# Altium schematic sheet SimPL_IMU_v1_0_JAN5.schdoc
size 302 x 236 mm
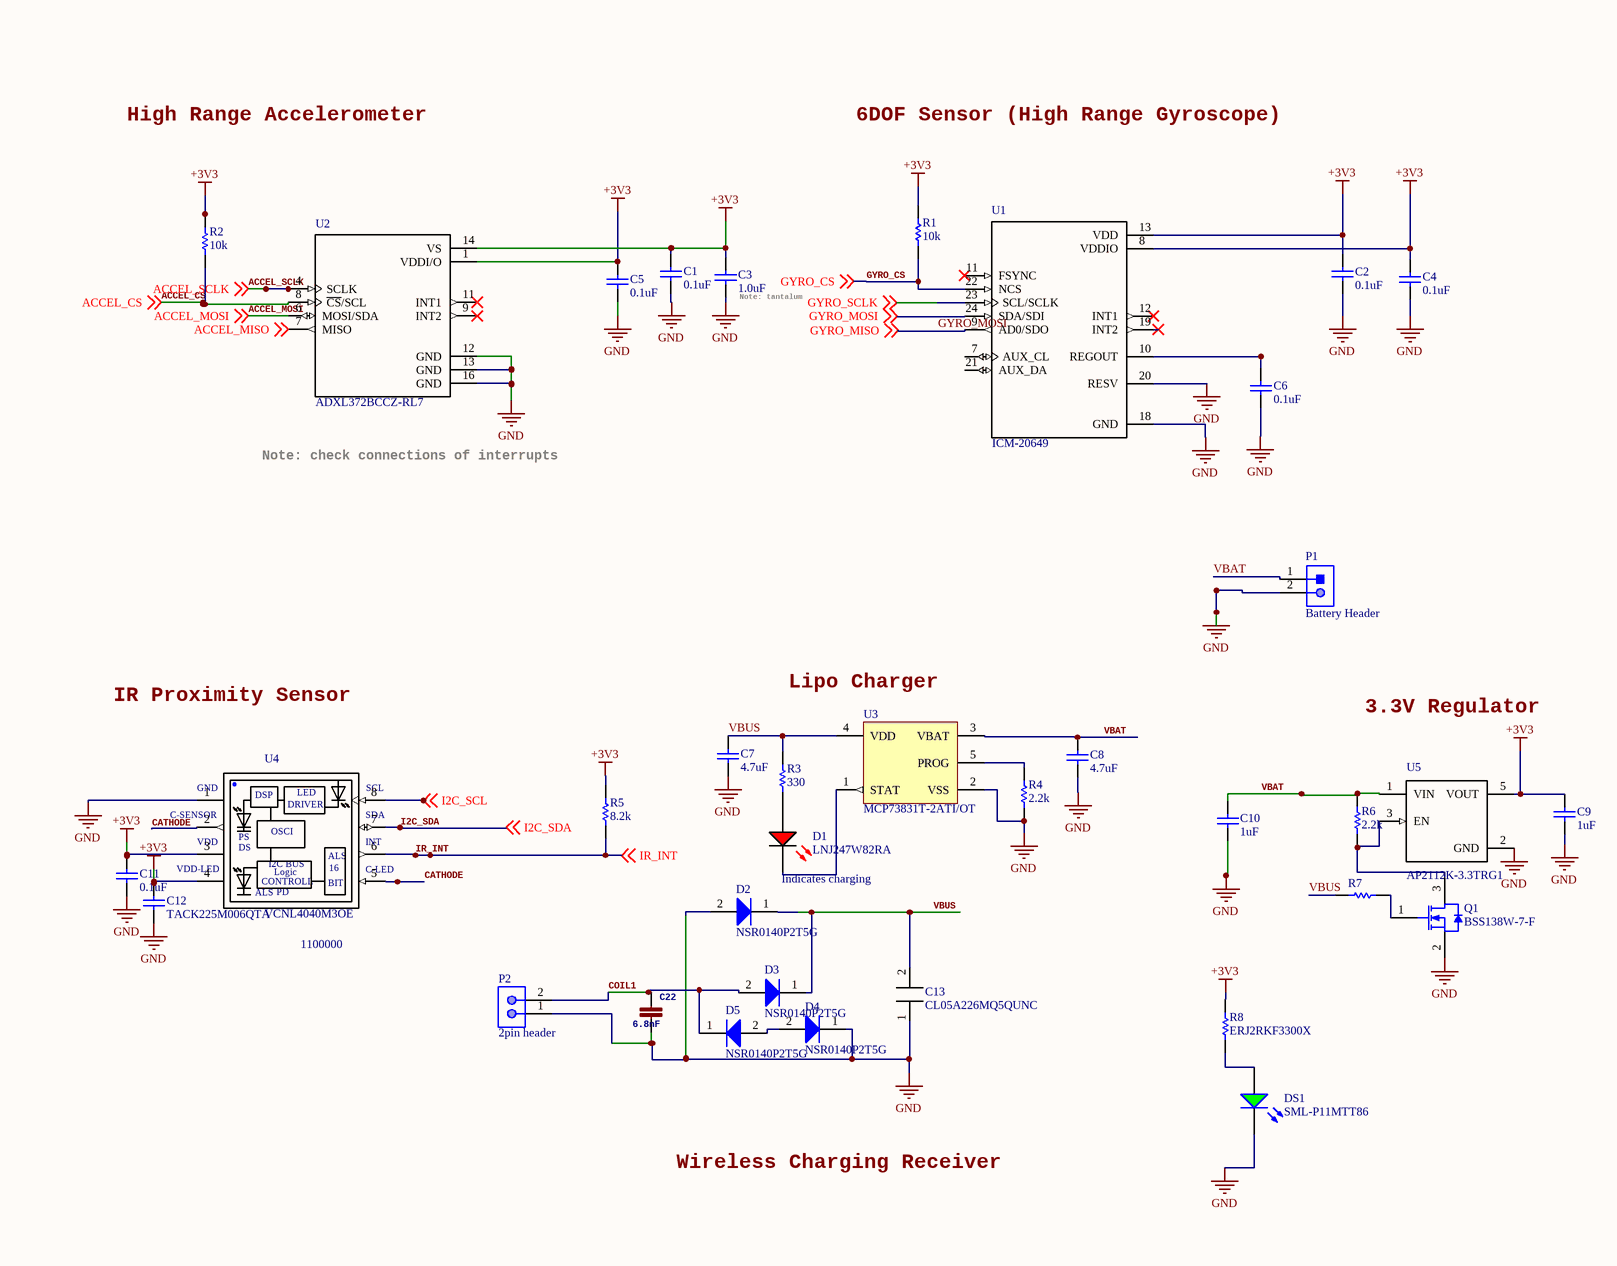
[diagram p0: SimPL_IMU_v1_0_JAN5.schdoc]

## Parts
C1  0.1uF  [CAPC0603X33X15LL03T05]
C2  0.1uF  [CAPC0603X33X15LL03T05]
C3  1.0uF  [CAPC1005X70X10LL20T00]
C4  0.1uF  [CAPC0603X33X15LL03T05]
C5  0.1uF  [CAPC0603X33X15LL03T05]
C6  0.1uF  [CAPC0603X33X15LL03T05]
C7  4.7uF  [CAPC1005X55X25NL05T10]
C8  4.7uF  [CAPC1005X55X25NL05T10]
C9  1uF  [CAPC1005X55X25NL05T10]
C10  1uF  [CAPC1005X55X25NL05T10]
C11  0.1uF  [CAPC0603X33X15LL03T05]
C12  TACK225M006QTA  [CAPC1005X70X10NL20T00]
C13  CL05A226MQ5QUNC  [*CAPC1005X55N]
C22  6.8nF  [0402]
D1  LNJ247W82RA  [PNSC-CHIP-2_V]
D2  NSR0140P2T5G  [ONSC-SOD-923-2-514AA-01_D_V]
D3  NSR0140P2T5G  [ONSC-SOD-923-2-514AA-01_D_V]
D4  NSR0140P2T5G  [ONSC-SOD-923-2-514AA-01_D_V]
D5  NSR0140P2T5G  [ONSC-SOD-923-2-514AA-01_D_V]
DS1  SML-P11MTT86  [ROHM-SML-P11MT_V]
P1  Battery Header  [JST-S2B-PH-K-S_V]
P2  2pin header  [AMPH-68000-102HLF_V]
Q1  BSS138W-7-F  [DIOD-SOT323-3_V]
R1  10k  [RESC0603X26X15NL03T05]
R2  10k  [RESC0603X26X15NL03T05]
R3  330  [RESC1005X40X25NL05T05]
R4  2.2k  [RESC1005X40X25NL10T10]
R5  8.2k  [RESC0201(0603)_L]
R6  2.2k  [RESC1005X40X25NL10T10]
R7  CRCW04022K20FKED  [RESC1005X40X25NL05T05]  (value not drawn)
R8  ERJ2RKF3300X  [RESC1005X40X25ML05T05]
U1  ICM-20649  [*QFN40P300X300X95-24N]
U2  ADXL372BCCZ-RL7  [*PQFN50P322X300X114-16N]
U3  MCP73831T-2ATI/OT  [SOT-23-OT5_M]
U4  VCNL4040M3OE  [*VISHAY_VCNL4040_4X2X1.1]
U5  AP2112K-3.3TRG1  [*SOT95P285X140-5N]

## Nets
+3V3: C1.2 C2.2 C3.2 C4.2 C5.2 C9.2 C11.2 C12.2 R1.2 R2.2 R5.2 R8.2 U1.8(VDDIO) U1.13(VDD) U2.1(VDDI/O) U2.14(VS) U4.3(VDD) U4.4(VDD-LED) U5.5(VOUT)
GND: C1.1 C2.1 C3.1 C4.1 C5.1 C6.1 C7.1 C8.1 C9.1 C10.1 C11.1 C12.1 C13.1 C22.2 D2.2(A) D4.1(K) DS1.2(K) P1.2 P2.1 Q1.2(S) R4.1 U1.18(GND) U1.20(RESV) U2.12(GND) U2.13(GND) U2.16(GND) U3.2(VSS) U4.1(GND) U5.2(GND)
ACCEL_CS: R2.1 U2.8(~{CS}/SCL) ; off-sheet ACCEL_CS
ACCEL_MISO: U2.7(MISO) ; off-sheet ACCEL_MISO
ACCEL_MOSI: U2.6(MOSI/SDA) ; off-sheet ACCEL_MOSI
ACCEL_SCLK: U2.4(SCLK) ; off-sheet ACCEL_SCLK
CATHODE: U4.2(C-SENSOR) U4.5(C-LED)
COIL1: C22.1 D3.2(A) D5.1(K) P2.2
GYRO_CS: R1.1 U1.22(NCS) ; off-sheet GYRO_CS
GYRO_MOSI: U1.9(AD0/SDO) U1.24(SDA/SDI) ; off-sheet GYRO_MISO, off-sheet GYRO_MOSI  [also labelled GYRO_MISO]
GYRO_SCLK: U1.23(SCL/SCLK) ; off-sheet GYRO_SCLK
I2C_SCL: U4.8(SCL) ; off-sheet I2C_SCL
I2C_SDA: U4.7(SDA) ; off-sheet I2C_SDA
IR_INT: R5.1 U4.6(INT) ; off-sheet IR_INT
VBAT: C8.2 C10.2 P1.1 R6.2 U3.3(VBAT) U5.1(VIN)
VBUS: C7.2 C13.2 D2.1(K) D3.1(K) R3.2 R7.1 U3.4(VDD)
NetC6_2: C6.2 U1.10(REGOUT)
NetD1_1: D1.1(ANODE) R3.1
NetD1_2: D1.2(CATHODE) U3.1(STAT)
NetD4_2: D4.2(A) D5.2(A)
NetDS1_1: DS1.1(A) R8.1
NetQ1_1: Q1.1(G) R7.2
NetQ1_3: Q1.3(D) R6.1 U5.3(EN)
NetR4_2: R4.2 U3.5(PROG)

Not connected (* = marked no-connect by the designer): U1 7(AUX_CL) 11(FSYNC)* 12(INT1)* 19(INT2)* 21(AUX_DA); U2 9(INT2)* 11(INT1)*

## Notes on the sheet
- High Range Accelerometer
- 6DOF Sensor (High Range Gyroscope)
- (near C3) Note: tantalum
- Note: check connections of interrupts
- IR Proximity Sensor
- (near U3) Lipo Charger
- 3.3V Regulator
- Indicates charging
- 1100000
- Wireless Charging Receiver
- Labels drawn without touching a wire or pin: I2C_SDA

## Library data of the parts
C1 C2 C4-C6 C11 = CMP-2010-01264-1: Part Number: GRM033R61A104KE15D; Manufacturer: Murata
C3 = CMP-2008-00066-1: Part Number: TACK105M010QTA; Manufacturer: AVX Interconnect / Elco
C7 C8 = CMP-2008-04549-1: Part Number: GRM155R60J475ME47D; Manufacturer: Murata
C9 C10 = CMP-2008-04556-1: Part Number: GRM155R61A105KE15D; Manufacturer: Murata
C12 = CMP-2008-00070-1: Manufacturer: AVX Interconnect / Elco
C13 = CL05A226MQ5QUNC: Capacitance: 22uF
C22 = 0.1UF-0402-16V-10%: 0.1ÂµF ceramic capacitors    A capacitor is a passive two-terminal electrical component used to store electrical energy temporarily in an electric field.; Part Number: CC0402KRX7R9BB682; GateName_1: G$1; SymbolName_1: CAP; DeviceSetName: 0.1UF; PROD_ID: CAP-12416
D1 = CMP-0456-00001-2: Hight Bright Surface Mounting Chip LED (Red), 55 mW, -30 to 85 degC, 1.0 x 0.5 x 0.2 mm  SMD; Manufacturer: Panasonic; Forward Voltage: 1.95 V; Reverse Current: 100 uA; Spectral half band width: 20 nm; Dominant Emission Wavelength: 630 nm; Luminous Intensity: 16 mcd; Peak Emission Wavelength: 645 nm
D2-D5 = CMP-1055-00493-1: Schottky Barrier Diode, 2-Pin SOD-923, Pb-Free, Tape and Reel; Manufacturer: On Semiconductor; IFSM Max (A): 0.5; Configuration: Single
DS1 = CMP-2000-07126-1: LED Green, 54 mW, 20 mA, -40 to 85 degC, 2-Pin SMD, RoHS, Tape and Reel; Manufacturer: Lite-On Inc.; Part Number: LTST-C170KGKT; Lens Type: Clear; Intensity: 2.1mcd; Forward Voltage: 1.9V; Forward (Drive) Current: 20mA
P1 = CMP-1755-00004-1: Male Header, Pitch 2 mm, 1 x 2 Position, Height 4.8 mm, Tail Length 3.4 mm, -25 to 85 degC, RoHS, Bulk; Case\Package: Radial; Tolerance: 20%; Capacitance: 10 uF; Voltage Rating (DC): 50 V
P2 = CMP-2000-05666-1: Male Header, Pitch 2.54 mm, 1 x 2 Position, Height 8.38 mm, Tail Length 2.41 mm, RoHS, Bulk; Number of Positions: 2; Insulation Resistance: 5000MOhms; Voltage Rating: 1.5kV; Mounting Angle: Vertical; Pitch: 2.54mm; Brand: FCI; Current Rating: 3A; Mating Post Length: 5.84mm
Q1 = CMP-2000-05968-1: N-Channel Enhancement Mode Mosfet, 50 V, 200 mA, -55 to 150 degC, 6-Pin SOT-323, RoHS, Tape and Reel; Typical Turn-Off Delay Time: 20ns; Number of Channels: 1Channel; Type: EnhancementModeFieldEffectTransistor; Brand: DiodesIncorporated; Vds - Drain-Source Breakdown Voltage: 75V; Vgs - Gate-Source Voltage: 20V; Rds On - Drain-Source Resistance: 1.4Ohms; Transistor Type: 1N-Channel; Configuration: Single; Unit Weight: 0.000212oz; Pd - Power Dissipation: 200mW; Id - Continuous Drain Current: 200mA; Forward Transconductance - Min: 0.1S
R1 R2 = CMP-2004-02627-1: Part Number: ERJ-1GEF1002C; Manufacturer: Panasonic
R3 = CMP-2002-08523-1: Manufacturer: Vishay Dale; Part Number: CRCW0402330RFKED
R4 R6 = CMP-2002-05881-1: Part Number: ERA2AEB222X; Manufacturer: Panasonic
R5 = CMP-1010-00519-1: 8K2 0.05W 1% 0201 (0603 Metric)  SMD; Part Number: ERJ-1GNF8201C; Manufacturer: Panasonic; Value: 8200.00 Ohm; Case-Metric: 0603; Case-EIA: 0201
R7 = CMP-2002-08452-1: Manufacturer: Vishay Dale
R8 = CMP-2002-01143-1: Manufacturer: Panasonic
U1 = ICM-20649: Wide-Range 6-Axis MEMS MotionTracking Device for Sports and High Impact Applications; MF: TDK InvenSense
U2 = ADXL372BCCZ-RL7: / Accelerometer Triple Â±200g 2.5V 16-Pin LGA T/R /; MF: Analog Devices
U3 = CMP-0133-00144-1: Miniature Single-Cell, Fully Integrated Li-Ion, Li-Polymer Charge Management Controller, 4.2V, 5-Pin SOT-23, Industrial Temperature, Tape and Reel
U4 = VCNL4040M3OE: VCNL4040 Series 3.6 V 200 mm 16 Bit I2C SMT Proximity and Ambient Light Sensor; MF: Vishay
U5 = AP2112K-3.3TRG1: AP2112 Series 0.6 A 3.3 V Fixed Output SMT LDO Linear Regulator - SOT23-5; MF: Diodes Inc.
